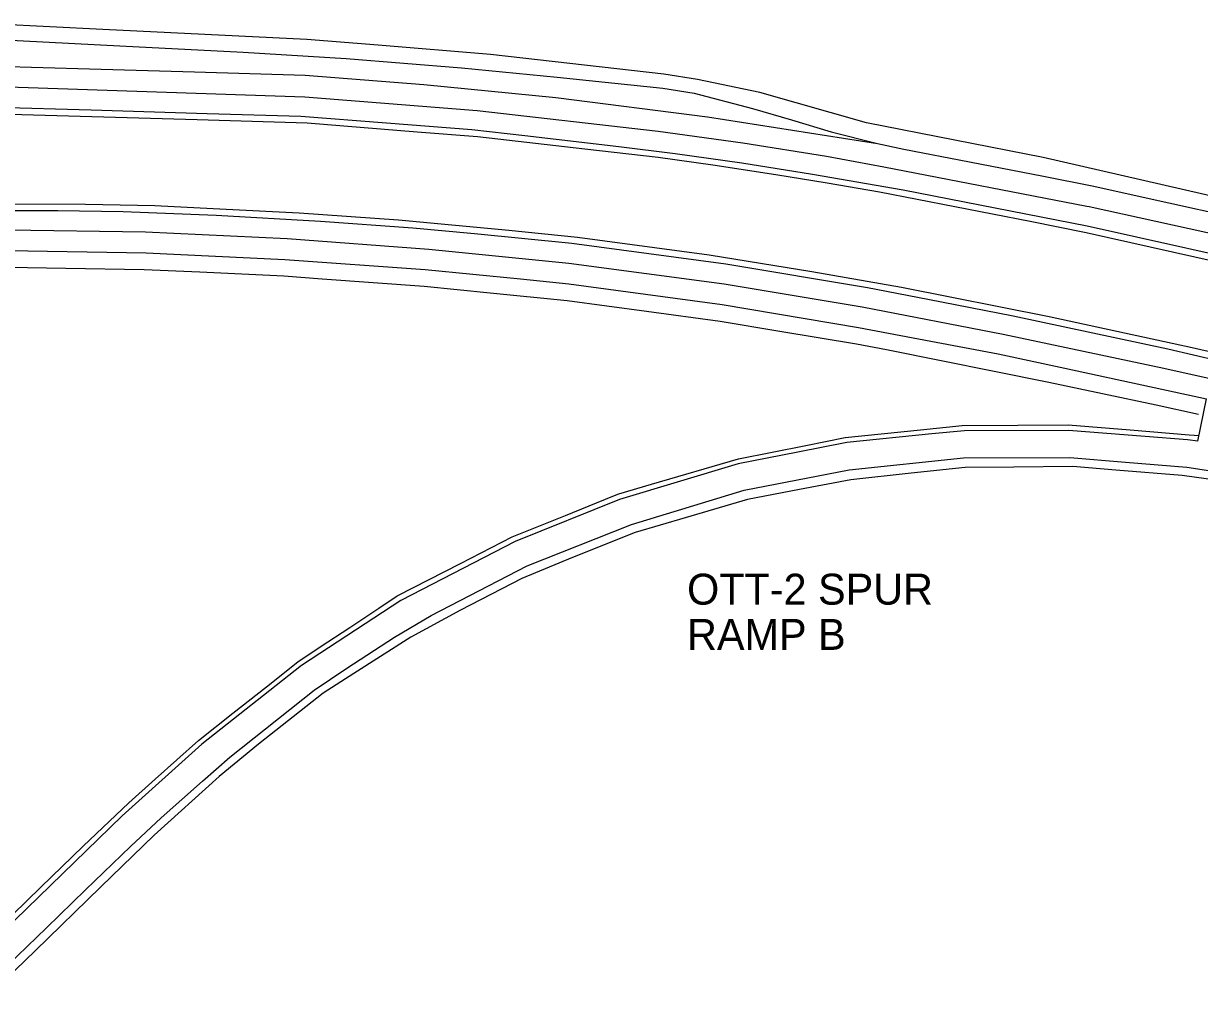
# Model space of a CAD drawing. Extents: x 1855721 to 1876784, y 662259 to 674089.
# Drawn here: x 1858417 to 1859101, y 672185 to 672758 of the extents above; entities that cross this region are included whole.
import ezdxf

# ---------------------------------------------------------------- set-up
doc = ezdxf.new("R2010")
doc.units = 0
for name, color, linetype in [('_CIVIL_CONSTRUCTION', 7, 'Continuous'), ('GE_X_Alignment_100_Bearings', 7, 'Continuous'), ('GE_X_Alignment_100_Curve_Data', 7, 'Continuous'), ('GE_X_Alignment_100_Distances', 7, 'Continuous'), ('SC_Scratch1', 7, 'Continuous')]:
    doc.layers.add(name, color=color, linetype=linetype)

msp = doc.modelspace()

# ---------------------------------------------------------------- linework, layer by layer
at = {"layer": '_CIVIL_CONSTRUCTION'}
msp.add_line((1859100.41, 672515.22), (1859105.37, 672539.82), dxfattribs=at)
for points in [[(1858112.66, 672758.13), (1858169.8, 672756.79), (1858231.98, 672755.13), (1858282.28, 672753.3), (1858340.58, 672751.17), (1858401.81, 672748.91), (1858472.96, 672745.19), (1858544.88, 672741.44), (1858604.68, 672737.71), (1858671.87, 672732.39), (1858727.54, 672726.94), (1858789, 672720.6), (1858807.15, 672717.53), (1858841.23, 672708.69), (1858863.84, 672702.01), (1858886.95, 672695.14), (1858913.87, 672688.3), (1858929.3, 672685.13), (1858967.42, 672677.7), (1859010.47, 672669.31), (1859038.76, 672663.79), (1859083.43, 672653.87), (1859118.51, 672646.08)], [(1857999.53, 672569.87), (1857996.61, 672595.79), (1858077.64, 672606.93), (1858118.31, 672610.94), (1858159.97, 672614.97), (1858232.24, 672620.65), (1858252.87, 672621.9), (1858302.14, 672623.96), (1858335.21, 672625.08), (1858407.95, 672626.18), (1858488.25, 672624.81), (1858569.03, 672620.88), (1858650.77, 672615.02), (1858706.13, 672609.52), (1858734.28, 672606.71), (1858823.5, 672594.64), (1858902.94, 672581.37), (1858944.96, 672573.37), (1858984.12, 672565.92), (1859022.95, 672557.68), (1859105.37, 672539.8)], [(1858385.07, 672188.63), (1858430.28, 672231.98), (1858453.11, 672254.11), (1858479.2, 672279.44), (1858497.08, 672295.95), (1858521.07, 672317.46), (1858537, 672331.26), (1858586.13, 672370.3), (1858605.1, 672383.02), (1858632.85, 672401.11), (1858654.22, 672413.83), (1858710, 672442.67), (1858770.72, 672466.74), (1858836.27, 672486.65), (1858897.5, 672498.5), (1858963.98, 672505.48), (1859025.82, 672505.6), (1859058.27, 672502.94), (1859093.99, 672499.95), (1859123, 672495.68)]]:
    msp.add_lwpolyline(points, dxfattribs=at)
at = {"layer": 'GE_X_Alignment_100_Bearings'}
for points in [[(1857530.71, 672587), (1857588.26, 672604.8), (1857614.97, 672612.46), (1857680.21, 672629.64), (1857730.24, 672642.05), (1857881.01, 672674.13), (1857975.46, 672689.54), (1858068.51, 672701.58), (1858163.83, 672711.37), (1858263.32, 672717.66), (1858402.31, 672721.48), (1858580.77, 672715.58), (1858680.94, 672707.57), (1858786.38, 672695.42), (1858835.49, 672688.75), (1858884.15, 672681), (1858917.61, 672674.84), (1859035.65, 672651.94), (1859037.18, 672651.78), (1859180.87, 672620.07)], [(1857520.47, 672496.11), (1857557.87, 672508.34), (1857658.83, 672538.03), (1857741.72, 672559.31), (1857825.42, 672578.08), (1857911.7, 672594.99), (1857994.46, 672608.07), (1858078.29, 672619.25), (1858158.12, 672627.41), (1858240.31, 672633.64), (1858323.44, 672636.86), (1858407.79, 672638.18), (1858487.86, 672636.86), (1858570.33, 672632.98), (1858652.9, 672626.79), (1858734.38, 672618.74), (1858824.74, 672606.62), (1858905, 672593.29), (1858987.11, 672577.5), (1859080.51, 672557.59), (1859107.52, 672551.69)]]:
    msp.add_lwpolyline(points, dxfattribs=at)
at = {"layer": 'GE_X_Alignment_100_Curve_Data'}
for points in [[(1859152.49, 672614.22), (1859035.9, 672640.26), (1858928.91, 672661.17), (1858876.12, 672670.38), (1858834.94, 672676.83), (1858796.15, 672682.34), (1858763.37, 672686.41), (1858708.61, 672692.74), (1858677.92, 672696.21), (1858628.11, 672700.17), (1858578.28, 672704.02), (1858523.78, 672705.66), (1858456.39, 672707.69), (1858400.9, 672709.27)], [(1859127.62, 672558.3), (1859082.9, 672568.68), (1858992.82, 672587.94), (1858943.28, 672597.62), (1858908.13, 672604.44), (1858825.6, 672618.19), (1858736.12, 672630.12), (1858679.44, 672635.77), (1858643.53, 672639.06), (1858589.72, 672643.01), (1858529.08, 672646.36), (1858474.95, 672648.52), (1858436.97, 672649.1), (1858388.49, 672649.24)], [(1859100.41, 672515.22), (1859094.27, 672516.03), (1859069.65, 672517.94), (1859025.12, 672521.4), (1858964.59, 672521.21), (1858945.62, 672519.36), (1858896.03, 672514.35), (1858867.63, 672508.81), (1858832.93, 672501.9), (1858763.75, 672481.15), (1858703.12, 672456.73), (1858636.63, 672422.56), (1858578.73, 672384.62), (1858520.76, 672338.91), (1858474.28, 672297.27), (1858376.94, 672202.76)]]:
    msp.add_lwpolyline(points, dxfattribs=at)
at = {"layer": 'GE_X_Alignment_100_Distances'}
msp.add_lwpolyline([(1858401.3, 672733.38), (1858455.37, 672731.82), (1858516.53, 672730.04), (1858580.86, 672728.18), (1858649.97, 672722.72), (1858726.75, 672715.09), (1858815.08, 672703.84), (1858913.87, 672688.3)], dxfattribs=at)
at = {"layer": 'SC_Scratch1'}
for points in [[(1859558.97, 672554.29), (1859010.24, 672680.2), (1858907.58, 672700.34), (1858845.49, 672717.95), (1858809.25, 672725.57), (1858789.59, 672728.75), (1858688.67, 672740.12), (1858623.26, 672745.51), (1858581.75, 672748.81), (1858463.04, 672754.74), (1858401.2, 672757.82)], [(1858402.25, 672705.67), (1858518.07, 672702.3), (1858582.01, 672700.36), (1858646.01, 672695.22), (1858681.1, 672692.36), (1858743.61, 672685.31), (1858786.24, 672680.46), (1858818.12, 672675.93), (1858854.75, 672670.31), (1858884.7, 672665.44), (1858915.14, 672660.22), (1859002.83, 672643.12), (1859035.44, 672636.65), (1859161.91, 672608.24)], [(1858385.33, 672653.22), (1858452.95, 672652.96), (1858493.47, 672652.24), (1858534.92, 672650.22), (1858577.47, 672648), (1858635.21, 672643.89), (1858699.43, 672637.92), (1858739.27, 672633.78), (1858815.92, 672623.51), (1858875.64, 672613.93), (1858927.84, 672604.76), (1859013.74, 672587.62), (1859097.05, 672569.69), (1859171.27, 672552.62)], [(1859100.81, 672530.59), (1859076.17, 672536.1), (1859013.56, 672549.37), (1858919.15, 672568.24), (1858901.61, 672571.64), (1858857.02, 672579.06), (1858822.4, 672584.83), (1858779.42, 672590.58), (1858733.24, 672596.76), (1858688.5, 672601.27), (1858650.11, 672605.11), (1858590.68, 672609.49), (1858568.38, 672611.13), (1858519.49, 672613.41), (1858487.21, 672614.9), (1858441.57, 672615.61), (1858407.97, 672616.13)], [(1858394.33, 672223.96), (1858427.02, 672255.7), (1858451.7, 672279.55), (1858478.24, 672304.76), (1858493.57, 672318.48), (1858518.86, 672341.12), (1858538.85, 672356.93), (1858558.33, 672372.34), (1858576.58, 672386.77), (1858589.68, 672395.45), (1858606.83, 672406.8), (1858623.81, 672418.04), (1858634.46, 672425.1), (1858671.23, 672443.99), (1858701.27, 672459.42), (1858732.28, 672472), (1858759.97, 672483.24), (1858763.34, 672484.5), (1858782.46, 672490.11), (1858833.1, 672504.88), (1858872.24, 672512.72), (1858895.1, 672517.21), (1858939.02, 672521.7), (1858963.28, 672524.19), (1858995.5, 672524.44), (1859024.93, 672524.67), (1859060.89, 672521.7), (1859095.27, 672518.88), (1859101.08, 672518.54)], [(1859120.45, 672491.22), (1859091.15, 672495.29), (1859052.54, 672498.39), (1859027.54, 672500.4), (1858993.32, 672500.11), (1858964.91, 672499.79), (1858933.6, 672496.46), (1858898.42, 672492.73), (1858868.55, 672487.02), (1858838.36, 672481.25), (1858802.07, 672470.6), (1858772.94, 672462.01), (1858736.34, 672447.56), (1858707.02, 672435.37), (1858671.3, 672416.9), (1858642.29, 672401.15), (1858609.25, 672380.04), (1858591.28, 672368.56), (1858553.8, 672338.85), (1858530.89, 672320.18), (1858492.99, 672285.97), (1858462, 672255.89), (1858423.82, 672218.62), (1858388.91, 672185.14)]]:
    msp.add_lwpolyline(points, dxfattribs=at)

# ---------------------------------------------------------------- texts
for s, p in [('OTT-2 SPUR', (1858803.11, 672420.07)), ('RAMP B', (1858803.11, 672393.74))]:
    msp.add_text(s, height=18, dxfattribs=at).set_placement(p)

doc.saveas('drawing.dxf')
